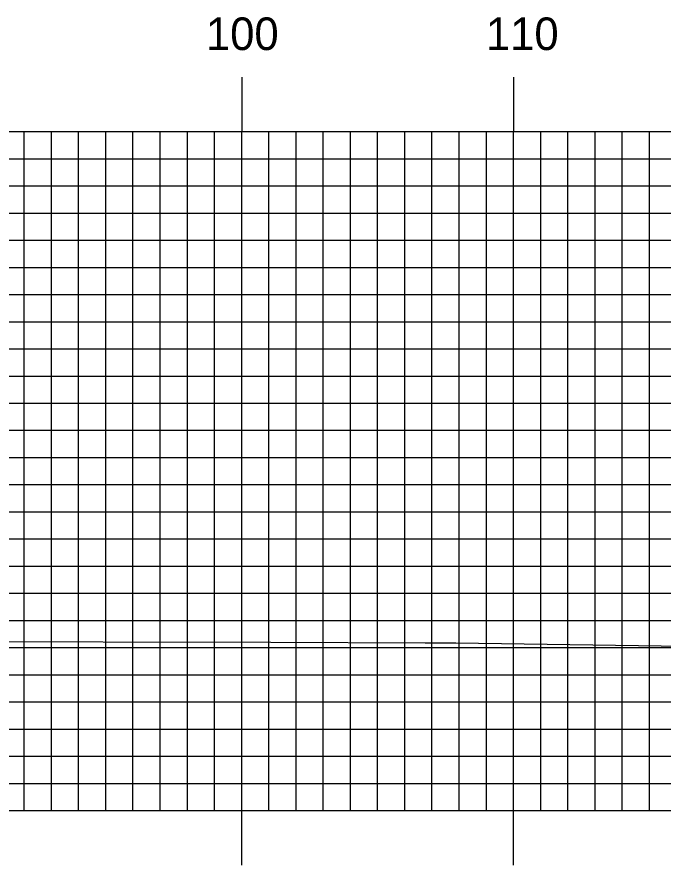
# Model space of a CAD drawing. Extents: x 1814915 to 1815259, y 442591 to 442811.
# Drawn here: x 1815172.75 to 1815196.52, y 442741.66 to 442772.88 of the extents above; entities that cross this region are included whole.
import ezdxf

# ---------------------------------------------------------------- set-up
doc = ezdxf.new("R2010")
doc.units = 0
for name, color, linetype in [('H_V ANNOTATION', 7, 'Continuous'), ('MAJOR', 7, 'Continuous'), ('MINOR', 7, 'Continuous'), ('S_Roadway_Centerline', 7, 'Continuous')]:
    doc.layers.add(name, color=color, linetype=linetype)

msp = doc.modelspace()

# ---------------------------------------------------------------- linework, layer by layer
at = {"layer": 'MAJOR'}
for p, q in [((1815181.021, 442770.669), (1815181.021, 442768.665)), ((1815191.021, 442770.669), (1815191.021, 442768.665)), ((1814941.021, 442768.665), (1815221.021, 442768.665)), ((1814941.021, 442768.665), (1815221.021, 442768.665)), ((1815181.021, 442743.665), (1815181.021, 442768.665)), ((1815191.021, 442743.665), (1815191.021, 442768.665)), ((1814941.021, 442763.665), (1815221.021, 442763.665)), ((1814941.021, 442758.665), (1815221.021, 442758.665)), ((1814941.021, 442753.665), (1815221.021, 442753.665)), ((1814941.021, 442748.665), (1815221.021, 442748.665)), ((1814941.021, 442743.665), (1815221.021, 442743.665)), ((1814941.021, 442743.665), (1815221.021, 442743.665)), ((1815181.021, 442741.661), (1815181.021, 442743.665)), ((1815191.021, 442741.661), (1815191.021, 442743.665))]:
    msp.add_line(p, q, dxfattribs=at)
at = {"layer": 'MINOR'}
for p, q in [((1815173.021, 442743.665), (1815173.021, 442768.665)), ((1815174.021, 442743.665), (1815174.021, 442768.665)), ((1815175.021, 442743.665), (1815175.021, 442768.665)), ((1815176.021, 442743.665), (1815176.021, 442768.665)), ((1815177.021, 442743.665), (1815177.021, 442768.665)), ((1815178.021, 442743.665), (1815178.021, 442768.665)), ((1815179.021, 442743.665), (1815179.021, 442768.665)), ((1815180.021, 442743.665), (1815180.021, 442768.665)), ((1815182.021, 442743.665), (1815182.021, 442768.665)), ((1815183.021, 442743.665), (1815183.021, 442768.665)), ((1815184.021, 442743.665), (1815184.021, 442768.665)), ((1815185.021, 442743.665), (1815185.021, 442768.665)), ((1815186.021, 442743.665), (1815186.021, 442768.665)), ((1815187.021, 442743.665), (1815187.021, 442768.665)), ((1815188.021, 442743.665), (1815188.021, 442768.665)), ((1815189.021, 442743.665), (1815189.021, 442768.665)), ((1815190.021, 442743.665), (1815190.021, 442768.665)), ((1815192.021, 442743.665), (1815192.021, 442768.665)), ((1815193.021, 442743.665), (1815193.021, 442768.665)), ((1815194.021, 442743.665), (1815194.021, 442768.665)), ((1815195.021, 442743.665), (1815195.021, 442768.665)), ((1815196.021, 442743.665), (1815196.021, 442768.665)), ((1814941.021, 442767.665), (1815221.021, 442767.665)), ((1814941.021, 442766.665), (1815221.021, 442766.665)), ((1814941.021, 442765.665), (1815221.021, 442765.665)), ((1814941.021, 442764.665), (1815221.021, 442764.665)), ((1814941.021, 442762.665), (1815221.021, 442762.665)), ((1814941.021, 442761.665), (1815221.021, 442761.665)), ((1814941.021, 442760.665), (1815221.021, 442760.665)), ((1814941.021, 442759.665), (1815221.021, 442759.665)), ((1814941.021, 442757.665), (1815221.021, 442757.665)), ((1814941.021, 442756.665), (1815221.021, 442756.665)), ((1814941.021, 442755.665), (1815221.021, 442755.665)), ((1814941.021, 442754.665), (1815221.021, 442754.665)), ((1814941.021, 442752.665), (1815221.021, 442752.665)), ((1814941.021, 442751.665), (1815221.021, 442751.665)), ((1814941.021, 442750.665), (1815221.021, 442750.665)), ((1814941.021, 442749.665), (1815221.021, 442749.665)), ((1814941.021, 442747.665), (1815221.021, 442747.665)), ((1814941.021, 442746.665), (1815221.021, 442746.665)), ((1814941.021, 442745.665), (1815221.021, 442745.665)), ((1814941.021, 442744.665), (1815221.021, 442744.665))]:
    msp.add_line(p, q, dxfattribs=at)
at = {"layer": 'S_Roadway_Centerline'}
msp.add_lwpolyline([(1815126.402, 442749.71), (1815137.574, 442749.683), (1815150.597, 442749.63), (1815154.07, 442749.585), (1815167.94, 442749.887), (1815169.729, 442749.89), (1815182.088, 442749.867), (1815187.773, 442749.84), (1815188.896, 442749.837), (1815204.004, 442749.615), (1815215.497, 442749.683), (1815220.278, 442749.598), (1815221.021, 442749.604)], dxfattribs=at)

# ---------------------------------------------------------------- texts
at = {"layer": 'H_V ANNOTATION'}
for s, p in [('100', (1815179.704, 442771.665)), ('110', (1815190.004, 442771.665))]:
    msp.add_text(s, height=1.2, dxfattribs=at).set_placement(p)

doc.saveas('drawing.dxf')
